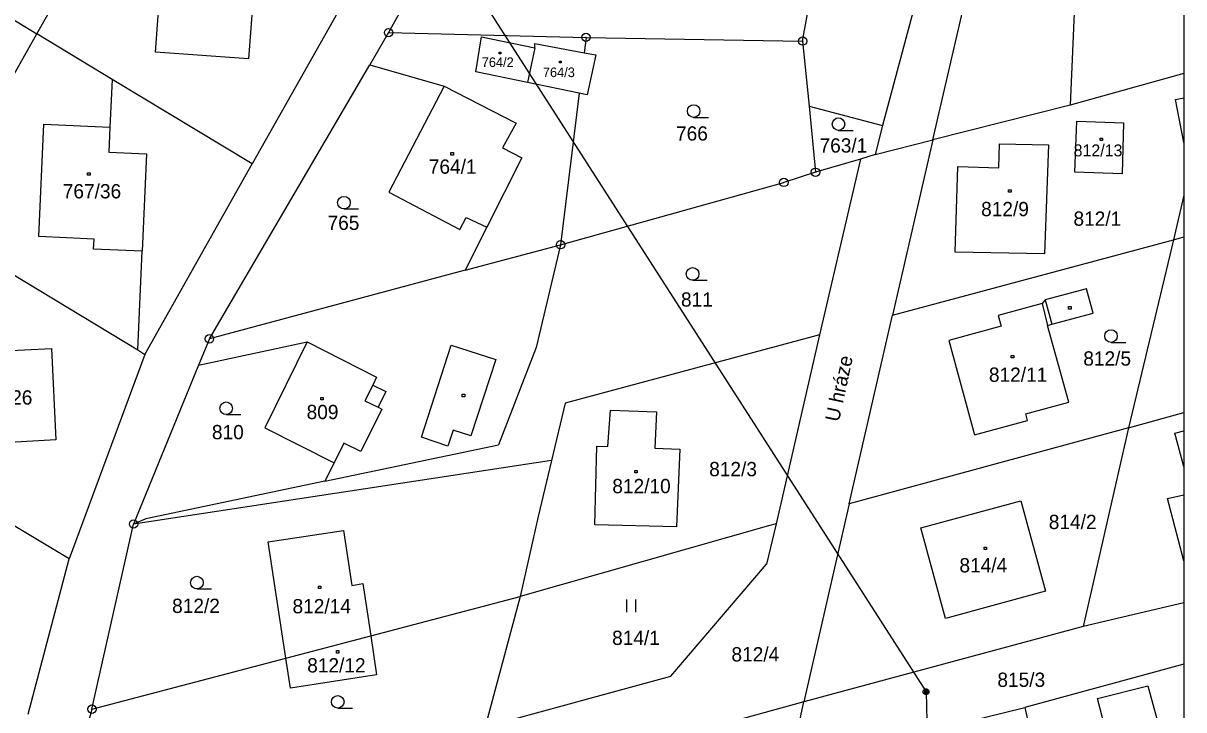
# Model space of a CAD drawing. Extents: x -468021 to -466942, y -1130484 to -1128584.
# Drawn here: x -467079.9 to -466941.7, y -1128906.2 to -1128824.5 of the extents above; entities that cross this region are included whole.
import ezdxf

# ---------------------------------------------------------------- set-up
doc = ezdxf.new("R2010")
doc.units = 0
doc.layers.add('Default', color=7, linetype='Continuous')
doc.layers.add('DKM', color=7, linetype='Continuous')

msp = doc.modelspace()

# ---------------------------------------------------------------- linework, layer by layer
at = {"layer": 'Default'}
msp.add_lwpolyline([(-468020.6, -1128583.91), (-466941.68, -1128583.91), (-466941.68, -1130484.41), (-468020.6, -1130484.41)], close=True, dxfattribs=at)
at = {"layer": 'DKM'}
for p, q in [((-466967.06, -1128797.49), (-466977.55, -1128836.65)), ((-467021.4, -1128798.6), (-467036.38, -1128825.6)), ((-466971.56, -1128838.36), (-466962.44, -1128799.03)), ((-467078.27, -1128825.75), (-467065.53, -1128803.14)), ((-466953.87, -1128802.05), (-466955.21, -1128834.24)), ((-467034.44, -1128807.4), (-466972.37, -1128904.07)), ((-467103.91, -1128810.16), (-467078.27, -1128825.75)), ((-466987.07, -1128826.6), (-466984.8, -1128814.2)), ((-467052.11, -1128815.76), (-467053.06, -1128828.72)), ((-467064.15, -1128827.91), (-467063.41, -1128818.15)), ((-467039.84, -1128818.58), (-467052.61, -1128841.21)), ((-467091.04, -1128848.41), (-467078.27, -1128825.75)), ((-467069.29, -1128831.16), (-467078.27, -1128825.75)), ((-467036.38, -1128825.6), (-467038.63, -1128829.44)), ((-467036.38, -1128825.6), (-467012.87, -1128826.16)), ((-467025.98, -1128830.28), (-467025.3, -1128826.08)), ((-467025.3, -1128826.08), (-467018.97, -1128827.4)), ((-467012.87, -1128826.16), (-467013.09, -1128827.99)), ((-467012.87, -1128826.16), (-466987.07, -1128826.6)), ((-466987.07, -1128826.6), (-466986.31, -1128834.37)), ((-467053.06, -1128828.72), (-467064.15, -1128827.91)), ((-467023.21, -1128827.92), (-467023.01, -1128827.92)), ((-467023.21, -1128828.12), (-467023.21, -1128827.92)), ((-467023.01, -1128827.92), (-467023.01, -1128828.12)), ((-467018.97, -1128827.4), (-467019.83, -1128831.55)), ((-467018.97, -1128827.4), (-467018.95, -1128826.88)), ((-467018.95, -1128826.88), (-467013.09, -1128827.99)), ((-467013.09, -1128827.99), (-467011.7, -1128828.25)), ((-467057.72, -1128862.05), (-467038.63, -1128829.44)), ((-467038.63, -1128829.44), (-467029.77, -1128831.99)), ((-467023.01, -1128828.12), (-467023.21, -1128828.12)), ((-467016.01, -1128829), (-467015.81, -1128829)), ((-467016.01, -1128829.2), (-467016.01, -1128829)), ((-467015.81, -1128829.2), (-467016.01, -1128829.2)), ((-467015.81, -1128829), (-467015.81, -1128829.2)), ((-467011.7, -1128828.25), (-467012.74, -1128833.02)), ((-467019.83, -1128831.55), (-467025.98, -1128830.28)), ((-466941.68, -1128830.45), (-466955.21, -1128834.24)), ((-467069.29, -1128831.16), (-467069.56, -1128836.84)), ((-467052.61, -1128841.21), (-467069.29, -1128831.16)), ((-467029.77, -1128831.99), (-467036.36, -1128844.6)), ((-467029.77, -1128831.99), (-467021.17, -1128836.37)), ((-467013.69, -1128832.82), (-467019.83, -1128831.55)), ((-467013.69, -1128832.82), (-467015.9, -1128850.85)), ((-467012.74, -1128833.02), (-467013.69, -1128832.82)), ((-466942.66, -1128833.54), (-466941.68, -1128833.35)), ((-466941.68, -1128838.67), (-466942.66, -1128833.54)), ((-466986.31, -1128834.37), (-466977.55, -1128836.65)), ((-466986.31, -1128834.37), (-466985.54, -1128842.22)), ((-466955.21, -1128834.24), (-466971.56, -1128838.36)), ((-467021.17, -1128836.37), (-467022.81, -1128839.3)), ((-467000.05, -1128835.69), (-466998.3, -1128835.69)), ((-467078.05, -1128849.88), (-467077.45, -1128836.49)), ((-467077.45, -1128836.49), (-467069.56, -1128836.84)), ((-467069.56, -1128836.84), (-467069.69, -1128839.84)), ((-466982.8, -1128837.24), (-466981.05, -1128837.24)), ((-466977.55, -1128836.65), (-466978.45, -1128840.09)), ((-466978.45, -1128840.09), (-466971.56, -1128838.36)), ((-466971.56, -1128838.36), (-466976.37, -1128859.23)), ((-466963.71, -1128841.68), (-466963.63, -1128838.83)), ((-466963.63, -1128838.83), (-466957.81, -1128838.97)), ((-466957.81, -1128838.97), (-466958.28, -1128851.94)), ((-466951.65, -1128838.15), (-466951.35, -1128838.15)), ((-466951.65, -1128838.45), (-466951.65, -1128838.15)), ((-466951.35, -1128838.45), (-466951.65, -1128838.45)), ((-466951.35, -1128838.15), (-466951.35, -1128838.45)), ((-467069.69, -1128839.84), (-467065.2, -1128840.04)), ((-467065.2, -1128840.04), (-467065.71, -1128851.63)), ((-467028.96, -1128839.88), (-467028.66, -1128839.88)), ((-467028.96, -1128840.18), (-467028.96, -1128839.88)), ((-467028.66, -1128840.18), (-467028.96, -1128840.18)), ((-467028.66, -1128839.88), (-467028.66, -1128840.18)), ((-467020.5, -1128840.51), (-467024.67, -1128848.77)), ((-467022.81, -1128839.3), (-467020.5, -1128840.51)), ((-466978.45, -1128840.09), (-466980.19, -1128840.67)), ((-467065.4, -1128863.9), (-467052.61, -1128841.21)), ((-466980.19, -1128840.67), (-466985.54, -1128842.22)), ((-466980.19, -1128840.67), (-466985.07, -1128861.57)), ((-466968.89, -1128851.74), (-466968.58, -1128841.53)), ((-466968.58, -1128841.53), (-466963.71, -1128841.68)), ((-467072.23, -1128842.27), (-467071.93, -1128842.27)), ((-467072.23, -1128842.57), (-467072.23, -1128842.27)), ((-467071.93, -1128842.57), (-467072.23, -1128842.57)), ((-467071.93, -1128842.27), (-467071.93, -1128842.57)), ((-466985.54, -1128842.22), (-466989.31, -1128843.43)), ((-467036.36, -1128844.6), (-467027.89, -1128849.03)), ((-467015.9, -1128850.85), (-466989.31, -1128843.43)), ((-466962.54, -1128844.31), (-466962.24, -1128844.31)), ((-466962.54, -1128844.61), (-466962.54, -1128844.31)), ((-466962.24, -1128844.61), (-466962.54, -1128844.61)), ((-466962.24, -1128844.31), (-466962.24, -1128844.61)), ((-466941.68, -1128844.93), (-466942.91, -1128850.25)), ((-467041.7, -1128846.59), (-467039.95, -1128846.59)), ((-467091.04, -1128848.41), (-467066.25, -1128863.38)), ((-467027.89, -1128849.03), (-467027.14, -1128847.59)), ((-467024.67, -1128848.77), (-467027.26, -1128853.89)), ((-467027.14, -1128847.59), (-467024.67, -1128848.77)), ((-467071.45, -1128850.17), (-467078.05, -1128849.88)), ((-467071.51, -1128851.37), (-467071.45, -1128850.17)), ((-466942.91, -1128850.25), (-466941.68, -1128849.92)), ((-467065.71, -1128851.63), (-467071.51, -1128851.37)), ((-467027.26, -1128853.89), (-467015.9, -1128850.85)), ((-467015.9, -1128850.85), (-467018.81, -1128863.07)), ((-466976.37, -1128859.23), (-466942.91, -1128850.25)), ((-466942.91, -1128850.25), (-466948.26, -1128872.63)), ((-467066.25, -1128863.38), (-467065.71, -1128851.63)), ((-466958.28, -1128851.94), (-466968.89, -1128851.74)), ((-467027.26, -1128853.89), (-467057.72, -1128862.05)), ((-467000.18, -1128855.07), (-466998.43, -1128855.07)), ((-466953.28, -1128856.09), (-466958.18, -1128857.42)), ((-466952.49, -1128858.99), (-466953.28, -1128856.09)), ((-466958.56, -1128857.84), (-466963.79, -1128859.26)), ((-466958.18, -1128857.42), (-466958.56, -1128857.84)), ((-466958.56, -1128857.84), (-466957.92, -1128860.46)), ((-466958.18, -1128857.42), (-466957.39, -1128860.32)), ((-466955.41, -1128858.21), (-466955.11, -1128858.21)), ((-466955.41, -1128858.51), (-466955.41, -1128858.21)), ((-466955.11, -1128858.21), (-466955.11, -1128858.51)), ((-466981.52, -1128881.69), (-466976.37, -1128859.23)), ((-466963.79, -1128859.26), (-466963.43, -1128860.55)), ((-466957.39, -1128860.32), (-466952.49, -1128858.99)), ((-466955.11, -1128858.51), (-466955.41, -1128858.51)), ((-466963.43, -1128860.55), (-466969.67, -1128862.26)), ((-466957.92, -1128860.46), (-466957.39, -1128860.32)), ((-466955.36, -1128869.61), (-466957.92, -1128860.46)), ((-467057.72, -1128862.05), (-467059.01, -1128865.2)), ((-467059.01, -1128865.2), (-467046.07, -1128862.42)), ((-467046.07, -1128862.42), (-467051.11, -1128872.63)), ((-467046.07, -1128862.42), (-467037.8, -1128866.63)), ((-466985.92, -1128861.8), (-467015.35, -1128869.73)), ((-466985.07, -1128861.57), (-466990.23, -1128884.06)), ((-466985.07, -1128861.57), (-466985.92, -1128861.8)), ((-466969.67, -1128862.26), (-466966.62, -1128873.48)), ((-466950.35, -1128862.47), (-466948.6, -1128862.47)), ((-467088.49, -1128863.79), (-467076.54, -1128863.21)), ((-467076.54, -1128863.21), (-467075.99, -1128874.08)), ((-467065.4, -1128863.9), (-467074.41, -1128888.26)), ((-467066.25, -1128863.38), (-467065.4, -1128863.9)), ((-467032.45, -1128873.75), (-467028.91, -1128862.79)), ((-467028.91, -1128862.79), (-467023.61, -1128864.53)), ((-467018.81, -1128863.07), (-467023.3, -1128874.68)), ((-467059.01, -1128865.2), (-467066.75, -1128884.1)), ((-467023.61, -1128864.53), (-467026.59, -1128873.6)), ((-466962.22, -1128864.03), (-466961.92, -1128864.03)), ((-466962.22, -1128864.33), (-466962.22, -1128864.03)), ((-466961.92, -1128864.33), (-466962.22, -1128864.33)), ((-466961.92, -1128864.03), (-466961.92, -1128864.33)), ((-467037.8, -1128866.63), (-467038.26, -1128867.55)), ((-467038.26, -1128867.55), (-467039.2, -1128869.44)), ((-467038.26, -1128867.55), (-467036.69, -1128868.33)), ((-467044.46, -1128869.03), (-467044.16, -1128869.03)), ((-467044.46, -1128869.33), (-467044.46, -1128869.03)), ((-467044.16, -1128869.33), (-467044.46, -1128869.33)), ((-467044.16, -1128869.03), (-467044.16, -1128869.33)), ((-467039.2, -1128869.44), (-467037.62, -1128870.19)), ((-467036.69, -1128868.33), (-467037.62, -1128870.19)), ((-467027.6, -1128868.64), (-467027.3, -1128868.64)), ((-467027.6, -1128868.94), (-467027.6, -1128868.64)), ((-467027.3, -1128868.94), (-467027.6, -1128868.94)), ((-467027.3, -1128868.64), (-467027.3, -1128868.94)), ((-467037.18, -1128870.41), (-467039.7, -1128875.48)), ((-467037.62, -1128870.19), (-467037.18, -1128870.41)), ((-467015.35, -1128869.73), (-467016.99, -1128876.54)), ((-467010.28, -1128874.86), (-467009.95, -1128870.54)), ((-467009.95, -1128870.54), (-467004.48, -1128870.75)), ((-467004.48, -1128870.75), (-467004.66, -1128875.06)), ((-466960.49, -1128871), (-466955.36, -1128869.61)), ((-466948.26, -1128872.63), (-466941.68, -1128870.84)), ((-467055.72, -1128871.07), (-467053.97, -1128871.07)), ((-466966.62, -1128873.48), (-466960.28, -1128871.76)), ((-466960.28, -1128871.76), (-466960.49, -1128871)), ((-467074.41, -1128888.26), (-467100.35, -1128872.65)), ((-467051.11, -1128872.63), (-467042.86, -1128876.8)), ((-467028.68, -1128872.91), (-467029.34, -1128874.84)), ((-467026.59, -1128873.6), (-467028.68, -1128872.91)), ((-466948.26, -1128872.63), (-466981.52, -1128881.69)), ((-466948.26, -1128872.63), (-466953.65, -1128896.29)), ((-466942.76, -1128873.3), (-466941.68, -1128873.01)), ((-466941.68, -1128877.27), (-466942.76, -1128873.3)), ((-467075.99, -1128874.08), (-467082.18, -1128874.43)), ((-467043.96, -1128879.01), (-467023.3, -1128874.68)), ((-467041.71, -1128874.48), (-467042.86, -1128876.8)), ((-467039.7, -1128875.48), (-467041.71, -1128874.48)), ((-467029.34, -1128874.84), (-467032.45, -1128873.75)), ((-467011.82, -1128884.2), (-467011.58, -1128874.83)), ((-467011.58, -1128874.83), (-467010.28, -1128874.86)), ((-467004.66, -1128875.06), (-467001.68, -1128875.17)), ((-467001.68, -1128875.17), (-467002.1, -1128884.45)), ((-467016.99, -1128876.54), (-467066.75, -1128884.1)), ((-467042.86, -1128876.8), (-467043.96, -1128879.01)), ((-467016.99, -1128876.54), (-467018.56, -1128883.22)), ((-467007.06, -1128877.72), (-467006.76, -1128877.72)), ((-467007.06, -1128878.02), (-467007.06, -1128877.72)), ((-467006.76, -1128877.72), (-467006.76, -1128878.02)), ((-467043.96, -1128879.01), (-467065.29, -1128883.48)), ((-467006.76, -1128878.02), (-467007.06, -1128878.02)), ((-466981.52, -1128881.69), (-466986.92, -1128905.26)), ((-466973, -1128884.56), (-466961.1, -1128881.33)), ((-466961.1, -1128881.33), (-466958.17, -1128892.11)), ((-466943.64, -1128881.08), (-466941.68, -1128880.62)), ((-466941.68, -1128888.49), (-466943.64, -1128881.08)), ((-467018.56, -1128883.22), (-467020.71, -1128892.74)), ((-467071.7, -1128906.14), (-467066.75, -1128884.1)), ((-467065.29, -1128883.48), (-467066.75, -1128884.1)), ((-466991.15, -1128884.32), (-467020.71, -1128892.74)), ((-467002.1, -1128884.45), (-467011.82, -1128884.2)), ((-466990.23, -1128884.06), (-466991.37, -1128888.87)), ((-466990.23, -1128884.06), (-466991.15, -1128884.32)), ((-466970.07, -1128895.35), (-466973, -1128884.56)), ((-467050.72, -1128886.22), (-467041.74, -1128884.86)), ((-467041.74, -1128884.86), (-467040.75, -1128891.4)), ((-467048.62, -1128900.08), (-467050.72, -1128886.22)), ((-466965.46, -1128886.85), (-466965.16, -1128886.85)), ((-466965.46, -1128887.15), (-466965.46, -1128886.85)), ((-466965.16, -1128887.15), (-466965.46, -1128887.15)), ((-466965.16, -1128886.85), (-466965.16, -1128887.15)), ((-467079.29, -1128906.72), (-467074.41, -1128888.26)), ((-467002.75, -1128902.2), (-466991.37, -1128888.87)), ((-467044.74, -1128891.49), (-467044.44, -1128891.49)), ((-467044.74, -1128891.79), (-467044.74, -1128891.49)), ((-467044.44, -1128891.49), (-467044.44, -1128891.79)), ((-467040.75, -1128891.4), (-467039.46, -1128891.2)), ((-467039.46, -1128891.2), (-467038.51, -1128897.42)), ((-467059.21, -1128891.82), (-467057.46, -1128891.82)), ((-467044.44, -1128891.79), (-467044.74, -1128891.79)), ((-467038.51, -1128897.42), (-467020.71, -1128892.74)), ((-467020.71, -1128892.74), (-467024.88, -1128908.23)), ((-466958.17, -1128892.11), (-466970.07, -1128895.35)), ((-467007.99, -1128894.58), (-467007.99, -1128893.08)), ((-467006.99, -1128893.08), (-467006.99, -1128894.58)), ((-466941.68, -1128893.47), (-466953.65, -1128896.29)), ((-466953.65, -1128896.29), (-466986.92, -1128905.26)), ((-467048.62, -1128900.08), (-467038.51, -1128897.42)), ((-467038.51, -1128897.42), (-467037.81, -1128902.04)), ((-467042.59, -1128899.16), (-467042.29, -1128899.16)), ((-467042.59, -1128899.46), (-467042.59, -1128899.16)), ((-467042.29, -1128899.46), (-467042.59, -1128899.46)), ((-467042.29, -1128899.16), (-467042.29, -1128899.46)), ((-467071.7, -1128906.14), (-467048.62, -1128900.08)), ((-467048.08, -1128903.65), (-467048.62, -1128900.08)), ((-466941.68, -1128900.79), (-466960.6, -1128905.94)), ((-467037.81, -1128902.04), (-467048.08, -1128903.65)), ((-467024.88, -1128908.23), (-467002.75, -1128902.2)), ((-466972.71, -1128904), (-466972.64, -1128903.87)), ((-466972.71, -1128904.14), (-466972.71, -1128904)), ((-466972.64, -1128903.87), (-466972.57, -1128903.8)), ((-466972.57, -1128903.8), (-466972.44, -1128903.74)), ((-466972.57, -1128903.94), (-466972.57, -1128904.2)), ((-466972.44, -1128903.74), (-466972.3, -1128903.74)), ((-466972.44, -1128904.27), (-466972.44, -1128903.87)), ((-466972.44, -1128903.87), (-466972.3, -1128903.87)), ((-466972.37, -1128904.07), (-466969.51, -1129007.7)), ((-466972.3, -1128903.74), (-466972.17, -1128903.8)), ((-466972.3, -1128903.87), (-466972.3, -1128904.27)), ((-466972.17, -1128903.8), (-466972.1, -1128903.87)), ((-466972.17, -1128904.2), (-466972.17, -1128903.94)), ((-466972.1, -1128903.87), (-466972.04, -1128904)), ((-466972.04, -1128904), (-466972.04, -1128904.14)), ((-466951.95, -1128904.88), (-466945.97, -1128903.37)), ((-466945.97, -1128903.37), (-466943.7, -1128911.67)), ((-466986.92, -1128905.26), (-466996.58, -1128907.92)), ((-466988.5, -1128912.43), (-466986.92, -1128905.26)), ((-466972.64, -1128904.27), (-466972.71, -1128904.14)), ((-466972.57, -1128904.34), (-466972.64, -1128904.27)), ((-466972.57, -1128904.2), (-466972.44, -1128904.27)), ((-466972.44, -1128904.41), (-466972.57, -1128904.34)), ((-466972.3, -1128904.41), (-466972.44, -1128904.41)), ((-466972.3, -1128904.27), (-466972.17, -1128904.2)), ((-466972.17, -1128904.34), (-466972.3, -1128904.41)), ((-466972.1, -1128904.27), (-466972.17, -1128904.34)), ((-466972.04, -1128904.14), (-466972.1, -1128904.27)), ((-466950.46, -1128910.64), (-466951.95, -1128904.88)), ((-467071.7, -1128906.14), (-467074.34, -1128915.95)), ((-467042.43, -1128906.02), (-467040.68, -1128906.02)), ((-466988.57, -1128912.76), (-466960.6, -1128905.94)), ((-466960.6, -1128905.94), (-466956.01, -1128926.89))]:
    msp.add_line(p, q, dxfattribs=at)
msp.add_lwpolyline([(-466954.64, -1128842.22), (-466954.41, -1128836.14), (-466948.86, -1128836.32), (-466949.01, -1128842.41), (-466954.64, -1128842.22)], dxfattribs=at)
for centre, radius in [((-467036.38, -1128825.6), 0.5), ((-467036.38, -1128825.6), 0.01), ((-467012.87, -1128826.16), 0.5), ((-467012.87, -1128826.16), 0.01), ((-466987.07, -1128826.6), 0.5), ((-466987.07, -1128826.6), 0.01), ((-467000.05, -1128834.94), 0.75), ((-466982.8, -1128836.49), 0.75), ((-466985.54, -1128842.22), 0.5), ((-466989.31, -1128843.43), 0.5), ((-466985.54, -1128842.22), 0.01), ((-466989.31, -1128843.43), 0.01), ((-467041.7, -1128845.84), 0.75), ((-467015.9, -1128850.85), 0.5), ((-467015.9, -1128850.85), 0.01), ((-467000.18, -1128854.32), 0.75), ((-466950.35, -1128861.72), 0.75), ((-467057.72, -1128862.05), 0.5), ((-467057.72, -1128862.05), 0.01), ((-467055.72, -1128870.32), 0.75), ((-467066.75, -1128884.1), 0.5), ((-467066.75, -1128884.1), 0.01), ((-467059.21, -1128891.07), 0.75), ((-467042.43, -1128905.27), 0.75), ((-467071.7, -1128906.14), 0.5), ((-467071.7, -1128906.14), 0.01)]:
    msp.add_circle(centre, radius, dxfattribs=at)

# ---------------------------------------------------------------- texts
for s, height, p in [('764/2', 1.14, (-467025.29, -1128829.69)), ('764/3', 1.14, (-467018.01, -1128830.89)), ('766', 1.7, (-467002.15, -1128838.45)), ('763/1', 1.7, (-466985.06, -1128839.88)), ('812/13', 1.42, (-466954.8, -1128840.33)), ('764/1', 1.7, (-467031.59, -1128842.4)), ('767/36', 1.7, (-467075.18, -1128845.33)), ('812/9', 1.7, (-466965.82, -1128847.45)), ('765', 1.7, (-467043.65, -1128849.09)), ('812/1', 1.7, (-466954.82, -1128848.59)), ('811', 1.7, (-467001.56, -1128858.22)), ('812/5', 1.7, (-466953.65, -1128865.24)), ('812/11', 1.7, (-466964.89, -1128867.17)), ('767/26', 1.7, (-467085.75, -1128869.88)), ('809', 1.7, (-467046.14, -1128871.61)), ('810', 1.7, (-467057.42, -1128874.01)), ('812/3', 1.7, (-466998.2, -1128878.41)), ('812/10', 1.7, (-467009.74, -1128880.43)), ('814/2', 1.7, (-466957.76, -1128884.7)), ('814/4', 1.7, (-466968.4, -1128889.86)), ('812/2', 1.7, (-467062.16, -1128894.69)), ('812/14', 1.7, (-467047.82, -1128894.73)), ('814/1', 1.7, (-467009.76, -1128898.5)), ('812/4', 1.7, (-466995.55, -1128900.46)), ('812/12', 1.7, (-467046.07, -1128901.77)), ('815/3', 1.7, (-466963.88, -1128903.49))]:
    msp.add_text(s, height=height, dxfattribs=at).set_placement(p)
msp.add_text('U hráze', height=1.7, rotation=77.7571, dxfattribs=at).set_placement((-466982.76, -1128872.02))

doc.saveas('drawing.dxf')
